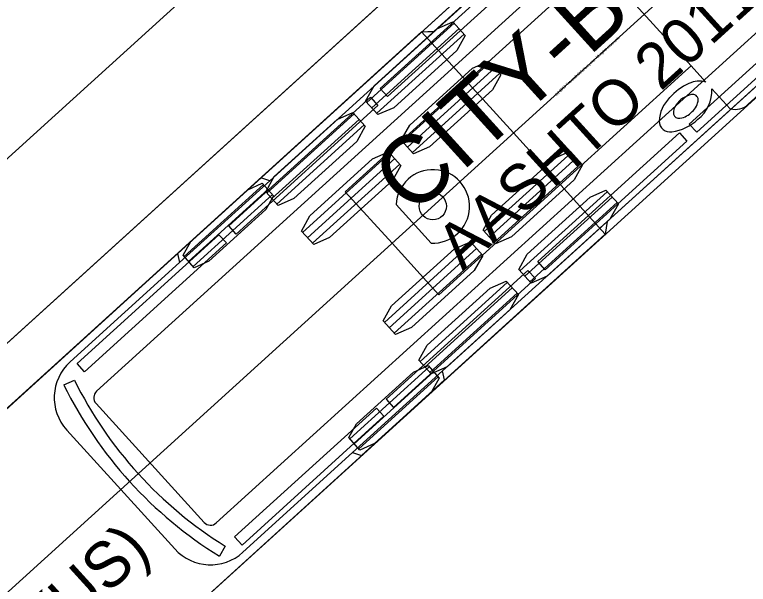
# Model space of a CAD drawing. Extents: x 1639988 to 1641860, y 841974 to 844187.
# Drawn here: x 1640743.86 to 1640766.69, y 844064.75 to 844082.48 of the extents above; entities that cross this region are included whole.
import ezdxf

# ---------------------------------------------------------------- set-up
doc = ezdxf.new("R2010")
doc.units = 0
for name, color, linetype in [('Scratch_Level_1', 7, 'Continuous'), ('Scratch_Level_2', 7, 'Continuous'), ('Scratch_Level_3', 7, 'Continuous'), ('Scratch_Level_4', 7, 'Continuous'), ('Scratch_Level_5', 7, 'Continuous'), ('Scratch_Level_6', 7, 'Continuous')]:
    doc.layers.add(name, color=color, linetype=linetype)

msp = doc.modelspace()

# ---------------------------------------------------------------- linework, layer by layer
at = {"layer": 'Scratch_Level_1'}
for p, q in [((1640767.683, 844099.846), (1640700.815, 844039.107)), ((1640606.388, 843939.823), (1640771.592, 844089.887)), ((1640764.905, 844080.888), (1640761.994, 844084.094)), ((1640757.534, 844082.212), (1640754.82, 844079.746)), ((1640757.688, 844082.042), (1640754.974, 844079.577)), ((1640757.842, 844081.872), (1640755.128, 844079.407)), ((1640758.643, 844080.99), (1640755.929, 844078.525)), ((1640758.797, 844080.821), (1640756.083, 844078.355)), ((1640758.951, 844080.651), (1640756.237, 844078.186)), ((1640754.425, 844079.388), (1640751.711, 844076.922)), ((1640754.579, 844079.218), (1640751.865, 844076.753)), ((1640754.733, 844079.048), (1640752.019, 844076.583)), ((1640755.534, 844078.166), (1640752.82, 844075.701)), ((1640761.187, 844078.19), (1640758.473, 844075.724)), ((1640755.688, 844077.997), (1640752.974, 844075.531)), ((1640761.341, 844078.02), (1640758.627, 844075.555)), ((1640755.842, 844077.827), (1640753.128, 844075.362)), ((1640761.495, 844077.851), (1640758.781, 844075.385)), ((1640762.296, 844076.968), (1640759.582, 844074.503)), ((1640762.45, 844076.799), (1640759.736, 844074.333)), ((1640755.731, 844076.564), (1640756.817, 844075.368)), ((1640762.604, 844076.629), (1640759.89, 844074.164)), ((1640758.078, 844075.366), (1640755.364, 844072.9)), ((1640758.232, 844075.196), (1640755.518, 844072.731)), ((1640758.386, 844075.027), (1640755.672, 844072.561)), ((1640759.187, 844074.144), (1640756.473, 844071.679)), ((1640759.342, 844073.975), (1640756.627, 844071.509)), ((1640759.496, 844073.805), (1640756.781, 844071.34))]:
    msp.add_line(p, q, dxfattribs=at)
for points in [[(1640808.793, 844131.447), (1640706.365, 844038.416), (1640702.379, 844034.843), (1640698.36, 844031.302), (1640694.302, 844027.802), (1640690.201, 844024.347), (1640686.055, 844020.942), (1640681.863, 844017.59), (1640677.628, 844014.295), (1640673.351, 844011.058), (1640669.032, 844007.881), (1640664.674, 844004.765), (1640660.276, 844001.71), (1640655.842, 843998.712), (1640651.385, 843995.755), (1640642.436, 843989.91), (1640624.5, 843978.327)], [(1640625.143, 843962.655), (1640720.123, 844048.882), (1640725.922, 844042.999), (1640720.615, 844049.33), (1640756.518, 844081.938), (1640756.914, 844081.958), (1640771.863, 844095.537), (1640777.242, 844089.616), (1640762.294, 844076.037), (1640762.236, 844075.649), (1640699.249, 844018.366), (1640667.744, 843989.646), (1640652.018, 843975.261), (1640636.326, 843960.847), (1640628.497, 843953.624)], [(1640765.367, 844080.38), (1640764.906, 844080.888), (1640764.729, 844080.728), (1640757.059, 844073.761), (1640755.603, 844075.364), (1640754.147, 844076.966), (1640761.817, 844083.934), (1640761.993, 844084.094), (1640761.532, 844084.602)], [(1640770.828, 844082.156), (1640770.764, 844082.098), (1640770.764, 844082.095), (1640770.801, 844081.7), (1640770.801, 844081.697), (1640770.713, 844081.617), (1640770.712, 844081.618), (1640770.418, 844082.323), (1640770.494, 844082.392), (1640770.74, 844082.145), (1640770.742, 844082.145), (1640770.8, 844082.199), (1640770.801, 844082.2), (1640770.801, 844082.201), (1640770.82, 844082.234), (1640770.82, 844082.235), (1640770.518, 844083.17), (1640766.686, 844079.689)], [(1640723.06, 844040.059), (1640723.074, 844040.043), (1640723.126, 844040.09), (1640727.32, 844043.902), (1640762.236, 844075.649), (1640759.377, 844078.794), (1640756.518, 844081.938), (1640721.602, 844050.191), (1640717.409, 844046.378), (1640717.357, 844046.33), (1640717.371, 844046.314)], [(1640766.125, 844079.546), (1640765.556, 844080.171)]]:
    msp.add_lwpolyline(points, dxfattribs=at)
for points in [[(1640757.495, 844082.254), (1640757.88, 844081.83), (1640757.616, 844081.358), (1640755.662, 844079.582), (1640755.166, 844079.365), (1640754.781, 844079.788), (1640755.045, 844080.261), (1640757, 844082.036)], [(1640758.605, 844081.032), (1640758.989, 844080.609), (1640758.725, 844080.136), (1640756.771, 844078.361), (1640756.275, 844078.144), (1640755.891, 844078.567), (1640756.155, 844079.04), (1640758.109, 844080.815)], [(1640754.387, 844079.43), (1640754.771, 844079.006), (1640754.507, 844078.534), (1640752.553, 844076.759), (1640752.057, 844076.541), (1640751.672, 844076.964), (1640751.937, 844077.437), (1640753.891, 844079.212)], [(1640755.496, 844078.208), (1640755.881, 844077.785), (1640755.616, 844077.312), (1640753.662, 844075.537), (1640753.166, 844075.32), (1640752.782, 844075.743), (1640753.046, 844076.216), (1640755, 844077.991)], [(1640761.149, 844078.232), (1640761.533, 844077.808), (1640761.269, 844077.336), (1640759.315, 844075.561), (1640758.819, 844075.343), (1640758.435, 844075.766), (1640758.699, 844076.239), (1640760.653, 844078.014)], [(1640762.258, 844077.011), (1640762.643, 844076.587), (1640762.379, 844076.114), (1640760.424, 844074.339), (1640759.929, 844074.122), (1640759.544, 844074.545), (1640759.808, 844075.018), (1640761.762, 844076.793)], [(1640758.04, 844075.408), (1640758.424, 844074.984), (1640758.16, 844074.512), (1640756.206, 844072.737), (1640755.71, 844072.519), (1640755.326, 844072.943), (1640755.59, 844073.415), (1640757.544, 844075.19)], [(1640759.149, 844074.187), (1640759.534, 844073.763), (1640759.27, 844073.29), (1640757.316, 844071.515), (1640756.82, 844071.298), (1640756.435, 844071.721), (1640756.699, 844072.194), (1640758.653, 844073.969)]]:
    msp.add_lwpolyline(points, close=True, dxfattribs=at)
msp.add_circle((1640756.87, 844076.515), 0.424, dxfattribs=at)
for centre, radius, start, end in [((1640765.165, 844079.68), 0.729, 73.9281, 116.4421), ((1640765.534, 844078.747), 1.73, 113.6255, 138.424), ((1640764.421, 844080.119), 1.136, 307.8294, 2.6207), ((1640765.056, 844079.269), 0.732, 100.8423, 147.0768), ((1640764.959, 844079.823), 0.169, 3.6976, 103.8163), ((1640765.042, 844079.092), 1.136, 134.9659, 176.4866), ((1640764.605, 844079.859), 0.522, 310.0811, 357.2452), ((1640764.715, 844079.428), 0.362, 138.9131, 187.954), ((1640766.27, 844080.148), 0.619, 256.4109, 312.2526), ((1640764.523, 844079.422), 0.172, 194.7984, 281.949), ((1640764.453, 844079.91), 0.664, 279.1251, 317.3468), ((1640764.254, 844079.172), 0.346, 181.8448, 278.8579), ((1640764.129, 844080.235), 1.416, 277.2546, 314.3224), ((1640756.872, 844076.51), 1.143, 267.2506, 177.2506)]:
    msp.add_arc(centre, radius, start, end, dxfattribs=at)
at = {"layer": 'Scratch_Level_2'}
for p, q in [((1640767.683, 844099.846), (1640700.815, 844039.107)), ((1640606.388, 843939.823), (1640771.592, 844089.887))]:
    msp.add_line(p, q, dxfattribs=at)
msp.add_lwpolyline([(1640821.873, 844143.329), (1640711.577, 844043.147), (1640707.605, 844039.571), (1640703.608, 844036.018), (1640699.578, 844032.494), (1640693.5, 844027.235), (1640689.408, 844023.771), (1640685.265, 844020.368), (1640681.075, 844017.026), (1640676.839, 844013.744), (1640672.558, 844010.522), (1640668.235, 844007.361), (1640663.871, 844004.261), (1640659.466, 844001.222), (1640655.021, 843998.244), (1640650.538, 843995.327), (1640648.282, 843993.891), (1640639.353, 843988.021), (1640630.409, 843982.187), (1640612.503, 843970.59)], dxfattribs=at)
at = {"layer": 'Scratch_Level_3'}
for p, q in [((1640767.683, 844099.846), (1640700.815, 844039.107)), ((1640606.388, 843939.823), (1640771.592, 844089.887)), ((1640764.905, 844080.888), (1640761.994, 844084.094)), ((1640757.534, 844082.212), (1640754.82, 844079.746)), ((1640757.688, 844082.042), (1640754.974, 844079.577)), ((1640757.842, 844081.872), (1640755.128, 844079.407)), ((1640758.643, 844080.99), (1640755.929, 844078.525)), ((1640758.797, 844080.821), (1640756.083, 844078.355)), ((1640758.951, 844080.651), (1640756.237, 844078.186)), ((1640754.425, 844079.388), (1640751.711, 844076.922)), ((1640754.579, 844079.218), (1640751.865, 844076.753)), ((1640754.733, 844079.048), (1640752.019, 844076.583)), ((1640755.534, 844078.166), (1640752.82, 844075.701)), ((1640761.187, 844078.19), (1640758.473, 844075.724)), ((1640755.688, 844077.997), (1640752.974, 844075.531)), ((1640761.341, 844078.02), (1640758.627, 844075.555)), ((1640755.842, 844077.827), (1640753.128, 844075.362)), ((1640761.495, 844077.851), (1640758.781, 844075.385)), ((1640762.296, 844076.968), (1640759.582, 844074.503)), ((1640762.45, 844076.799), (1640759.736, 844074.333)), ((1640755.731, 844076.564), (1640756.817, 844075.368)), ((1640762.604, 844076.629), (1640759.89, 844074.164)), ((1640758.078, 844075.366), (1640755.364, 844072.9)), ((1640758.232, 844075.196), (1640755.518, 844072.731)), ((1640758.386, 844075.027), (1640755.672, 844072.561)), ((1640759.187, 844074.144), (1640756.473, 844071.679)), ((1640759.342, 844073.975), (1640756.627, 844071.509)), ((1640759.496, 844073.805), (1640756.781, 844071.34))]:
    msp.add_line(p, q, dxfattribs=at)
for points in [[(1640821.879, 844143.334), (1640711.577, 844043.147), (1640707.605, 844039.571), (1640703.608, 844036.018), (1640699.578, 844032.494), (1640693.5, 844027.235), (1640689.408, 844023.771), (1640685.265, 844020.368), (1640681.075, 844017.026), (1640676.839, 844013.744), (1640672.558, 844010.522), (1640668.235, 844007.361), (1640663.871, 844004.261), (1640659.466, 844001.222), (1640655.021, 843998.244), (1640650.538, 843995.327), (1640648.282, 843993.891), (1640639.353, 843988.021), (1640630.409, 843982.187), (1640612.503, 843970.59)], [(1640617.994, 843956.15), (1640720.123, 844048.882), (1640725.922, 844042.999), (1640720.617, 844049.331), (1640756.518, 844081.938), (1640756.914, 844081.959), (1640771.863, 844095.537), (1640777.235, 844089.609), (1640762.294, 844076.037), (1640762.236, 844075.649), (1640699, 844018.144), (1640667.491, 843989.427), (1640651.762, 843975.046), (1640636.064, 843960.637), (1640620.414, 843946.185)], [(1640765.367, 844080.38), (1640764.906, 844080.888), (1640764.729, 844080.728), (1640757.059, 844073.761), (1640755.603, 844075.364), (1640754.147, 844076.966), (1640761.817, 844083.934), (1640761.993, 844084.094), (1640761.532, 844084.602)], [(1640770.828, 844082.156), (1640770.764, 844082.098), (1640770.764, 844082.095), (1640770.801, 844081.7), (1640770.801, 844081.697), (1640770.713, 844081.617), (1640770.712, 844081.618), (1640770.418, 844082.323), (1640770.494, 844082.392), (1640770.74, 844082.145), (1640770.742, 844082.145), (1640770.8, 844082.199), (1640770.801, 844082.2), (1640770.801, 844082.201), (1640770.82, 844082.234), (1640770.82, 844082.235), (1640770.518, 844083.17), (1640766.686, 844079.689)], [(1640723.058, 844040.06), (1640723.073, 844040.044), (1640723.125, 844040.091), (1640727.319, 844043.903), (1640762.236, 844075.649), (1640759.377, 844078.794), (1640756.518, 844081.938), (1640721.601, 844050.192), (1640717.408, 844046.379), (1640717.356, 844046.332), (1640717.37, 844046.316)], [(1640766.125, 844079.546), (1640765.556, 844080.171)]]:
    msp.add_lwpolyline(points, dxfattribs=at)
for points in [[(1640757.495, 844082.254), (1640757.88, 844081.83), (1640757.616, 844081.358), (1640755.662, 844079.582), (1640755.166, 844079.365), (1640754.781, 844079.788), (1640755.045, 844080.261), (1640757, 844082.036)], [(1640758.605, 844081.032), (1640758.989, 844080.609), (1640758.725, 844080.136), (1640756.771, 844078.361), (1640756.275, 844078.144), (1640755.891, 844078.567), (1640756.155, 844079.04), (1640758.109, 844080.815)], [(1640754.387, 844079.43), (1640754.771, 844079.006), (1640754.507, 844078.534), (1640752.553, 844076.759), (1640752.057, 844076.541), (1640751.672, 844076.964), (1640751.937, 844077.437), (1640753.891, 844079.212)], [(1640755.496, 844078.208), (1640755.881, 844077.785), (1640755.616, 844077.312), (1640753.662, 844075.537), (1640753.166, 844075.32), (1640752.782, 844075.743), (1640753.046, 844076.216), (1640755, 844077.991)], [(1640761.149, 844078.232), (1640761.533, 844077.808), (1640761.269, 844077.336), (1640759.315, 844075.561), (1640758.819, 844075.343), (1640758.435, 844075.766), (1640758.699, 844076.239), (1640760.653, 844078.014)], [(1640762.258, 844077.011), (1640762.643, 844076.587), (1640762.379, 844076.114), (1640760.424, 844074.339), (1640759.929, 844074.122), (1640759.544, 844074.545), (1640759.808, 844075.018), (1640761.762, 844076.793)], [(1640758.04, 844075.408), (1640758.424, 844074.984), (1640758.16, 844074.512), (1640756.206, 844072.737), (1640755.71, 844072.519), (1640755.326, 844072.943), (1640755.59, 844073.415), (1640757.544, 844075.19)], [(1640759.149, 844074.187), (1640759.534, 844073.763), (1640759.27, 844073.29), (1640757.316, 844071.515), (1640756.82, 844071.298), (1640756.435, 844071.721), (1640756.699, 844072.194), (1640758.653, 844073.969)]]:
    msp.add_lwpolyline(points, close=True, dxfattribs=at)
msp.add_circle((1640756.87, 844076.515), 0.424, dxfattribs=at)
for centre, radius, start, end in [((1640765.165, 844079.68), 0.729, 73.9281, 116.4421), ((1640765.534, 844078.747), 1.73, 113.6255, 138.424), ((1640764.421, 844080.119), 1.136, 307.8294, 2.6207), ((1640765.056, 844079.269), 0.732, 100.8423, 147.0768), ((1640764.959, 844079.823), 0.169, 3.6976, 103.8163), ((1640765.042, 844079.092), 1.136, 134.9659, 176.4866), ((1640764.605, 844079.859), 0.522, 310.0811, 357.2452), ((1640764.715, 844079.428), 0.362, 138.9131, 187.954), ((1640766.27, 844080.148), 0.619, 256.4109, 312.2526), ((1640764.523, 844079.422), 0.172, 194.7984, 281.949), ((1640764.453, 844079.91), 0.664, 279.1251, 317.3468), ((1640764.254, 844079.172), 0.346, 181.8448, 278.8579), ((1640764.129, 844080.235), 1.416, 277.2546, 314.3224), ((1640756.872, 844076.51), 1.143, 267.2506, 177.2506)]:
    msp.add_arc(centre, radius, start, end, dxfattribs=at)
at = {"layer": 'Scratch_Level_4'}
for p, q in [((1640767.683, 844099.846), (1640700.815, 844039.107)), ((1640773.38, 844095.253), (1640746.413, 844070.757)), ((1640750.137, 844066.657), (1640777.104, 844091.153)), ((1640606.388, 843939.823), (1640771.592, 844089.887)), ((1640751.799, 844077.31), (1640748.996, 844074.765)), ((1640751.603, 844077.19), (1640749.135, 844074.949)), ((1640751.743, 844077.036), (1640749.275, 844074.794)), ((1640751.883, 844076.881), (1640749.415, 844074.64)), ((1640756.757, 844071.515), (1640754.29, 844069.274)), ((1640757.176, 844071.391), (1640754.374, 844068.845)), ((1640756.898, 844071.361), (1640754.43, 844069.12)), ((1640757.038, 844071.207), (1640754.57, 844068.965)), ((1640746.395, 844070.375), (1640749.755, 844066.676))]:
    msp.add_line(p, q, dxfattribs=at)
for points in [[(1640794.762, 844118.702), (1640731.801, 844061.511), (1640716.025, 844047.15), (1640708.096, 844039.978), (1640700.164, 844032.774), (1640696.182, 844029.177), (1640694.17, 844027.4), (1640692.142, 844025.64), (1640690.1, 844023.895), (1640688.044, 844022.166), (1640685.973, 844020.453), (1640683.889, 844018.756), (1640681.792, 844017.074), (1640677.559, 844013.757), (1640673.278, 844010.502), (1640668.952, 844007.311), (1640664.585, 844004.185), (1640660.181, 844001.125), (1640655.74, 843998.13), (1640651.263, 843995.2), (1640646.749, 843992.333), (1640637.704, 843986.649), (1640628.694, 843980.932)], [(1640624.434, 843962.029), (1640656.03, 843990.671), (1640773.916, 844097.74), (1640779.631, 844091.448), (1640653.136, 843976.524), (1640637.372, 843962.177), (1640621.63, 843947.812)], [(1640772.554, 844096.163), (1640770.423, 844094.228), (1640770.029, 844094.21), (1640767.439, 844091.856), (1640767.383, 844091.466), (1640751.799, 844077.31), (1640751.524, 844077.4), (1640748.933, 844075.047), (1640748.996, 844074.765), (1640745.586, 844071.667)], [(1640750.964, 844065.747), (1640754.374, 844068.845), (1640754.649, 844068.755), (1640757.239, 844071.108), (1640757.176, 844071.391), (1640772.76, 844085.546), (1640773.154, 844085.564), (1640775.745, 844087.918), (1640775.8, 844088.308)], [(1640745.395, 844070.951), (1640745.722, 844071.105)], [(1640745.485, 844069.548), (1640748.845, 844065.849)], [(1640750.417, 844065.936), (1640750.232, 844065.625)]]:
    msp.add_lwpolyline(points, dxfattribs=at)
for points in [[(1640759.878, 844083.935), (1640759.646, 844084.19), (1640755.235, 844080.184), (1640755.467, 844079.928)], [(1640764.848, 844079.073), (1640765.08, 844078.817), (1640769.491, 844082.825), (1640769.259, 844083.079)], [(1640750.753, 844075.646), (1640750.521, 844075.902), (1640754.933, 844079.909), (1640755.164, 844079.653)], [(1640764.545, 844078.797), (1640764.777, 844078.542), (1640760.366, 844074.535), (1640760.134, 844074.791)], [(1640751.568, 844077.228), (1640751.918, 844076.843), (1640751.677, 844076.414), (1640749.901, 844074.8), (1640749.45, 844074.602), (1640749.101, 844074.987), (1640749.341, 844075.417), (1640751.117, 844077.03)], [(1640746.039, 844071.364), (1640745.807, 844071.62), (1640750.219, 844075.627), (1640750.45, 844075.371)], [(1640755.42, 844070.509), (1640755.652, 844070.253), (1640760.063, 844074.261), (1640759.831, 844074.515)], [(1640756.723, 844071.553), (1640757.072, 844071.168), (1640756.832, 844070.739), (1640755.056, 844069.125), (1640754.605, 844068.927), (1640754.255, 844069.312), (1640754.495, 844069.742), (1640756.272, 844071.355)], [(1640750.706, 844066.227), (1640750.938, 844065.971), (1640755.349, 844069.979), (1640755.117, 844070.233)]]:
    msp.add_lwpolyline(points, close=True, dxfattribs=at)
for centre, radius, start, end in [((1640746.595, 844070.557), 1.5, 132.2507, 222.2507), ((1640757.116, 844076.738), 12.711, 206.308, 238.1935), ((1640757.116, 844076.738), 13.073, 206.2778, 238.2237), ((1640746.595, 844070.557), 0.27, 132.2507, 222.2507), ((1640749.955, 844066.857), 0.27, 222.2507, 312.2507), ((1640749.955, 844066.857), 1.5, 222.2507, 312.2507)]:
    msp.add_arc(centre, radius, start, end, dxfattribs=at)
at = {"layer": 'Scratch_Level_5'}
for p, q in [((1640767.683, 844099.846), (1640700.815, 844039.107)), ((1640773.38, 844095.253), (1640746.413, 844070.757)), ((1640750.137, 844066.657), (1640777.104, 844091.153)), ((1640606.388, 843939.823), (1640771.592, 844089.887)), ((1640751.799, 844077.31), (1640748.996, 844074.765)), ((1640751.603, 844077.19), (1640749.135, 844074.949)), ((1640751.743, 844077.036), (1640749.275, 844074.794)), ((1640751.883, 844076.881), (1640749.415, 844074.64)), ((1640756.757, 844071.515), (1640754.29, 844069.274)), ((1640757.176, 844071.391), (1640754.374, 844068.845)), ((1640756.898, 844071.361), (1640754.43, 844069.12)), ((1640757.038, 844071.207), (1640754.57, 844068.965)), ((1640746.395, 844070.375), (1640749.755, 844066.676))]:
    msp.add_line(p, q, dxfattribs=at)
for points in [[(1640794.753, 844118.694), (1640731.801, 844061.511), (1640716.025, 844047.15), (1640708.096, 844039.978), (1640700.164, 844032.774), (1640696.182, 844029.177), (1640694.17, 844027.4), (1640692.142, 844025.64), (1640690.1, 844023.895), (1640688.044, 844022.166), (1640685.973, 844020.453), (1640683.889, 844018.756), (1640681.792, 844017.074), (1640677.559, 844013.757), (1640673.278, 844010.502), (1640668.952, 844007.311), (1640664.585, 844004.185), (1640660.181, 844001.125), (1640655.74, 843998.13), (1640651.263, 843995.2), (1640646.749, 843992.333), (1640637.704, 843986.649), (1640628.694, 843980.932)], [(1640624.434, 843962.029), (1640656.03, 843990.671), (1640773.916, 844097.74), (1640779.631, 844091.448), (1640653.136, 843976.524), (1640637.372, 843962.177), (1640621.63, 843947.812)], [(1640772.554, 844096.163), (1640770.423, 844094.228), (1640770.029, 844094.21), (1640767.439, 844091.856), (1640767.383, 844091.466), (1640751.799, 844077.31), (1640751.524, 844077.4), (1640748.933, 844075.047), (1640748.996, 844074.765), (1640745.586, 844071.667)], [(1640750.964, 844065.747), (1640754.374, 844068.845), (1640754.649, 844068.755), (1640757.239, 844071.108), (1640757.176, 844071.391), (1640772.76, 844085.546), (1640773.154, 844085.564), (1640775.745, 844087.918), (1640775.8, 844088.308)], [(1640745.395, 844070.951), (1640745.722, 844071.105)], [(1640745.485, 844069.548), (1640748.845, 844065.849)], [(1640750.417, 844065.936), (1640750.232, 844065.625)]]:
    msp.add_lwpolyline(points, dxfattribs=at)
for points in [[(1640759.878, 844083.935), (1640759.646, 844084.19), (1640755.235, 844080.184), (1640755.467, 844079.928)], [(1640764.848, 844079.073), (1640765.08, 844078.817), (1640769.491, 844082.825), (1640769.259, 844083.079)], [(1640750.753, 844075.646), (1640750.521, 844075.902), (1640754.933, 844079.909), (1640755.164, 844079.653)], [(1640764.545, 844078.797), (1640764.777, 844078.542), (1640760.366, 844074.535), (1640760.134, 844074.791)], [(1640751.568, 844077.228), (1640751.918, 844076.843), (1640751.677, 844076.414), (1640749.901, 844074.8), (1640749.45, 844074.602), (1640749.101, 844074.987), (1640749.341, 844075.417), (1640751.117, 844077.03)], [(1640746.039, 844071.364), (1640745.807, 844071.62), (1640750.219, 844075.627), (1640750.45, 844075.371)], [(1640755.42, 844070.509), (1640755.652, 844070.253), (1640760.063, 844074.261), (1640759.831, 844074.515)], [(1640756.723, 844071.553), (1640757.072, 844071.168), (1640756.832, 844070.739), (1640755.056, 844069.125), (1640754.605, 844068.927), (1640754.255, 844069.312), (1640754.495, 844069.742), (1640756.272, 844071.355)], [(1640750.706, 844066.227), (1640750.938, 844065.971), (1640755.349, 844069.979), (1640755.117, 844070.233)]]:
    msp.add_lwpolyline(points, close=True, dxfattribs=at)
for centre, radius, start, end in [((1640746.595, 844070.557), 1.5, 132.2507, 222.2507), ((1640757.116, 844076.738), 12.711, 206.308, 238.1935), ((1640757.116, 844076.738), 13.073, 206.2778, 238.2237), ((1640746.595, 844070.557), 0.27, 132.2507, 222.2507), ((1640749.955, 844066.857), 0.27, 222.2507, 312.2507), ((1640749.955, 844066.857), 1.5, 222.2507, 312.2507)]:
    msp.add_arc(centre, radius, start, end, dxfattribs=at)
at = {"layer": 'Scratch_Level_6'}
for p, q in [((1640767.683, 844099.846), (1640700.815, 844039.107)), ((1640773.38, 844095.253), (1640746.413, 844070.757)), ((1640750.137, 844066.657), (1640777.104, 844091.153)), ((1640606.388, 843939.823), (1640771.592, 844089.887)), ((1640751.799, 844077.31), (1640748.996, 844074.765)), ((1640751.603, 844077.19), (1640749.135, 844074.949)), ((1640751.743, 844077.036), (1640749.275, 844074.794)), ((1640751.883, 844076.881), (1640749.415, 844074.64)), ((1640756.757, 844071.515), (1640754.29, 844069.274)), ((1640757.176, 844071.391), (1640754.374, 844068.845)), ((1640756.898, 844071.361), (1640754.43, 844069.12)), ((1640757.038, 844071.207), (1640754.57, 844068.965)), ((1640746.395, 844070.375), (1640749.755, 844066.676))]:
    msp.add_line(p, q, dxfattribs=at)
for points in [[(1640794.776, 844118.715), (1640731.801, 844061.511), (1640716.025, 844047.15), (1640708.096, 844039.978), (1640700.164, 844032.774), (1640696.182, 844029.177), (1640694.17, 844027.4), (1640692.142, 844025.64), (1640690.1, 844023.895), (1640688.044, 844022.166), (1640685.973, 844020.453), (1640683.889, 844018.756), (1640681.792, 844017.074), (1640677.559, 844013.757), (1640673.278, 844010.502), (1640668.952, 844007.311), (1640664.585, 844004.185), (1640660.181, 844001.125), (1640655.74, 843998.13), (1640651.263, 843995.2), (1640646.749, 843992.333), (1640637.704, 843986.649), (1640628.694, 843980.932)], [(1640624.187, 843961.806), (1640655.783, 843990.447), (1640773.916, 844097.74), (1640779.631, 844091.448), (1640653.136, 843976.524), (1640637.372, 843962.177), (1640621.63, 843947.812)], [(1640772.554, 844096.163), (1640770.423, 844094.228), (1640770.029, 844094.21), (1640767.439, 844091.856), (1640767.383, 844091.466), (1640751.799, 844077.31), (1640751.524, 844077.4), (1640748.933, 844075.047), (1640748.996, 844074.765), (1640745.586, 844071.667)], [(1640750.964, 844065.747), (1640754.374, 844068.845), (1640754.649, 844068.755), (1640757.239, 844071.108), (1640757.176, 844071.391), (1640772.76, 844085.546), (1640773.154, 844085.564), (1640775.745, 844087.918), (1640775.8, 844088.308)], [(1640745.395, 844070.951), (1640745.722, 844071.105)], [(1640745.485, 844069.548), (1640748.845, 844065.849)], [(1640750.417, 844065.936), (1640750.232, 844065.625)]]:
    msp.add_lwpolyline(points, dxfattribs=at)
for points in [[(1640759.878, 844083.935), (1640759.646, 844084.19), (1640755.235, 844080.184), (1640755.467, 844079.928)], [(1640764.848, 844079.073), (1640765.08, 844078.817), (1640769.491, 844082.825), (1640769.259, 844083.079)], [(1640750.753, 844075.646), (1640750.521, 844075.902), (1640754.933, 844079.909), (1640755.164, 844079.653)], [(1640764.545, 844078.797), (1640764.777, 844078.542), (1640760.366, 844074.535), (1640760.134, 844074.791)], [(1640751.568, 844077.228), (1640751.918, 844076.843), (1640751.677, 844076.414), (1640749.901, 844074.8), (1640749.45, 844074.602), (1640749.101, 844074.987), (1640749.341, 844075.417), (1640751.117, 844077.03)], [(1640746.039, 844071.364), (1640745.807, 844071.62), (1640750.219, 844075.627), (1640750.45, 844075.371)], [(1640755.42, 844070.509), (1640755.652, 844070.253), (1640760.063, 844074.261), (1640759.831, 844074.515)], [(1640756.723, 844071.553), (1640757.072, 844071.168), (1640756.832, 844070.739), (1640755.056, 844069.125), (1640754.605, 844068.927), (1640754.255, 844069.312), (1640754.495, 844069.742), (1640756.272, 844071.355)], [(1640750.706, 844066.227), (1640750.938, 844065.971), (1640755.349, 844069.979), (1640755.117, 844070.233)]]:
    msp.add_lwpolyline(points, close=True, dxfattribs=at)
for centre, radius, start, end in [((1640746.595, 844070.557), 1.5, 132.2507, 222.2507), ((1640757.116, 844076.738), 12.711, 206.308, 238.1935), ((1640757.116, 844076.738), 13.073, 206.2778, 238.2237), ((1640746.595, 844070.557), 0.27, 132.2507, 222.2507), ((1640749.955, 844066.857), 0.27, 222.2507, 312.2507), ((1640749.955, 844066.857), 1.5, 222.2507, 312.2507)]:
    msp.add_arc(centre, radius, start, end, dxfattribs=at)

# ---------------------------------------------------------------- texts
at = {"layer": 'Scratch_Level_1'}
msp.add_text('AASHTO 2011 (US)', height=1.41667, rotation=42.2784, dxfattribs=at).set_placement((1640735.608, 844054.3))
at = {"layer": 'Scratch_Level_3'}
msp.add_text('AASHTO 2011 (US)', height=1.41667, rotation=42.2764, dxfattribs=at).set_placement((1640735.607, 844054.301))
at = {"layer": 'Scratch_Level_4'}
for s, height, p in [('AASHTO 2011 (US)', 1.41667, (1640757.804, 844074.482)), ('CITY-BUS', 2.125, (1640756.237, 844076.169)), ('(c) 2019 Transoft Solutions, Inc. All rights reserved.', 0.085, (1640760.715, 844079.95))]:
    msp.add_text(s, height=height, rotation=42.2507, dxfattribs=at).set_placement(p)
at = {"layer": 'Scratch_Level_5'}
for s, height, p in [('AASHTO 2011 (US)', 1.41667, (1640757.804, 844074.482)), ('CITY-BUS', 2.125, (1640756.237, 844076.169)), ('(c) 2019 Transoft Solutions, Inc. All rights reserved.', 0.085, (1640760.715, 844079.95))]:
    msp.add_text(s, height=height, rotation=42.2507, dxfattribs=at).set_placement(p)
at = {"layer": 'Scratch_Level_6'}
for s, height, p in [('AASHTO 2011 (US)', 1.41667, (1640757.804, 844074.482)), ('CITY-BUS', 2.125, (1640756.237, 844076.169)), ('(c) 2019 Transoft Solutions, Inc. All rights reserved.', 0.085, (1640760.715, 844079.95))]:
    msp.add_text(s, height=height, rotation=42.2507, dxfattribs=at).set_placement(p)

doc.saveas('drawing.dxf')
